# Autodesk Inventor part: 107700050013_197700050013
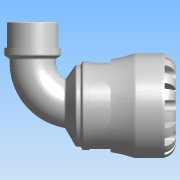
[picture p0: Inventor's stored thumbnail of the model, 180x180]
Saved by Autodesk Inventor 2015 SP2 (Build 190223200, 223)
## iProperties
Created: 2016-12
Part Number: 107700050013_197700050013
Material: PVC-Piping
Description: PLASSON 90° ELBOW WITH MALE INTEGRAL BRASS 50X1.1/4" SERIES 1
Document SubType Name: Modeling
Designer: KIM
Mass: 664.223 g
Surface Area: 733.008 cm^2
Volume: 474.445 cm^3
Density: 1.4 g/cm^3
Appearance: Smooth - White
Author: KIM
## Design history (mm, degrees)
derived "1077.ipt"
feature "Solid1::1077.ipt"
tag "TaggingFeature1"
body "Solid1"
other parameters: "d1" = 33.18, "d3" = 62.5, "d4" = 85, "d8" = 72.25, "d13" = 9, "d14" = 9, "d15" = 0, "d17" = 360 deg, "d19" = 8 deg, "d20" = 1, "d21" = 1, "d22" = 8 deg, "d24" = 0, "d26" = 360 deg, "d33" = 8.5, "d43" = 66.3, "d51" = 0.85, "d54" = 17.5, "d55" = 11, "d57" = 17.64, "d58" = 0, "d74" = 0, "d78" = 79, "d82" = 1, "d115" = 360 deg, "d207" = 90 deg, "d228" = 14.875, "d247" = 1.7, "d248" = 4.74, "d268" = 39.7375, "d269" = 4.74, "d270" = 116, "d276" = 41.91, "d277" = 21, "d278" = 46.101, "d279" = 68, "d280" = 27.3, "d281" = 6.2865, "d283" = 37.719, "d286" = 0, "d287" = 0, "d288" = 29.337, "d290" = 14.2905, "d292" = 30 deg, "d294" = 4.191, "d296" = 30 deg, "E_" = 85, "l_" = 79, "A_" = 116, "A_1" = 68, "l_2" = 21, "R_" = 41.91, "d9" = 11.25, "d11" = 85, "d12" = 62.5, "d289" = 29.337
